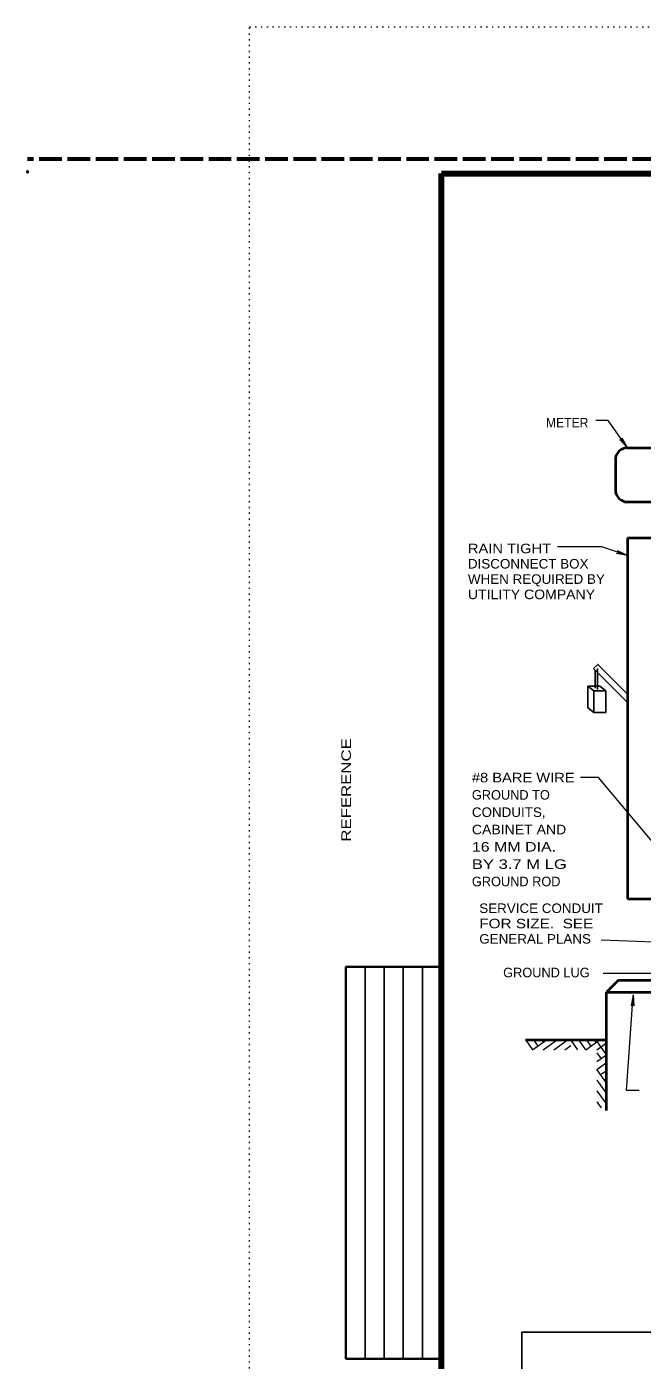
# Model space of a CAD drawing. Extents: x 312583 to 312854, y 144419 to 144597.
# Drawn here: x 312583.5 to 312632.5, y 144490.5 to 144596.8 of the extents above; entities that cross this region are included whole.
import ezdxf

# ---------------------------------------------------------------- set-up
doc = ezdxf.new("R2010")
doc.units = 0
doc.header["$LTSCALE"] = 0.3
doc.header["$PDMODE"] = 32
doc.header["$PDSIZE"] = 0.15
doc.linetypes.add('DOTTED', pattern=[1.5, 0.3, -1.2])
doc.linetypes.add('LONG_DASHED', pattern=[7.5, 6, -1.5])
doc.layers.add('1', color=7, linetype='Continuous', lineweight=25)
doc.layers.add('2', color=7, linetype='Continuous', lineweight=13)

msp = doc.modelspace()

# ---------------------------------------------------------------- linework, layer by layer
at = {"layer": '1', "linetype": 'DOTTED', "lineweight": 13}
for p, q in [((312601.2, 144596.7846), (312853.5, 144596.7846)), ((312601.2, 144418.5846), (312601.2, 144596.7846))]:
    msp.add_line(p, q, dxfattribs=at)
at = {"layer": '1', "linetype": 'LONG_DASHED', "lineweight": 60}
msp.add_line((312851.75, 144586.2246), (312583.526, 144586.2246), dxfattribs=at)
at = {"layer": '1', "lineweight": 158}
for p, q in [((312616.5, 144585.0846), (312849, 144585.0846)), ((312616.5, 144423.1446), (312616.5, 144585.0846))]:
    msp.add_line(p, q, dxfattribs=at)
at = {"layer": '1', "lineweight": 40}
for p, q in [((312631.3068, 144563.23), (312634.1818, 144563.23)), ((312630.3485, 144562.2716), (312630.3485, 144559.8796)), ((312631.3068, 144558.9213), (312634.1818, 144558.9213)), ((312631.3068, 144556.0616), (312631.3068, 144527.2963)), ((312631.3068, 144556.0616), (312636.8345, 144556.0616)), ((312631.3068, 144527.2963), (312636.8345, 144527.2963)), ((312630.5861, 144520.8256), (312629.6278, 144519.8673)), ((312629.6278, 144510.422), (312629.6278, 144519.8673)), ((312629.6278, 144519.8673), (312704.3778, 144519.8673)), ((312630.5861, 144520.8256), (312703.4195, 144520.8256)), ((312629.6278, 144516.034), (312623.1878, 144516.034))]:
    msp.add_line(p, q, dxfattribs=at)
at = {"layer": '1'}
for p, q in [((312631.3068, 144542.9363), (312628.6005, 144545.6426)), ((312628.7308, 144544.094), (312628.7308, 144545.5123)), ((312628.9301, 144545.6503), (312628.9301, 144543.9713)), ((312628.6235, 144543.864), (312628.1635, 144544.232)), ((312629.5818, 144543.864), (312629.1218, 144544.232)), ((312629.5818, 144543.864), (312628.6235, 144543.864)), ((312629.5818, 144543.864), (312629.5818, 144542.1313)), ((312628.6235, 144542.1313), (312628.1635, 144542.507)), ((312610.4087, 144490.6573), (312610.4087, 144521.8756)), ((312611.9315, 144490.6573), (312611.9315, 144521.8756)), ((312613.4543, 144490.6573), (312613.4543, 144521.8756)), ((312614.9772, 144490.6573), (312614.9772, 144521.8756)), ((312622.9059, 144492.7843), (312688.4513, 144492.7843)), ((312622.9059, 144492.7843), (312622.9059, 144445.8337))]:
    msp.add_line(p, q, dxfattribs=at)
at = {"layer": '1', "lineweight": 13}
msp.add_line((312639.8398, 144524.0303), (312628.9915, 144536.9563), dxfattribs=at)
at = {"layer": '1'}
for points in [[(312631.3068, 144543.611), (312628.9455, 144545.98), (312628.6005, 144545.6426)], [(312628.1635, 144542.507), (312628.1635, 144544.232), (312629.1218, 144544.232)], [(312628.6235, 144543.864), (312628.6235, 144542.1313), (312629.5818, 144542.1313)]]:
    msp.add_lwpolyline(points, dxfattribs=at)
at = {"layer": '1', "lineweight": 35}
msp.add_lwpolyline([(312616.5, 144490.6573), (312608.8858, 144490.6573), (312608.8858, 144521.8756), (312616.5, 144521.8756)], dxfattribs=at)
at = {"layer": '1', "lineweight": 40}
for centre, start, end in [((312631.3058, 144562.2735), 90, 180), ((312631.3058, 144559.8777), 180, 270)]:
    msp.add_arc(centre, 0.9583, start, end, dxfattribs=at)
at = {"layer": '1'}
msp.add_point((312583.526, 144585.2246), dxfattribs=at)
at = {"layer": '2'}
for p, q in [((312629.7658, 144565.4073), (312628.7998, 144565.4073)), ((312631.3068, 144563.23), (312629.7658, 144565.4073)), ((312630.7165, 144563.8816), (312630.9618, 144563.713)), ((312631.3068, 144563.23), (312630.7165, 144563.8816)), ((312630.8928, 144564.0043), (312630.9618, 144563.713)), ((312631.3068, 144563.23), (312630.8928, 144564.0043)), ((312629.2751, 144555.3333), (312625.7331, 144555.3333)), ((312631.3068, 144554.6433), (312629.2751, 144555.3333)), ((312630.5248, 144555.0266), (312630.7471, 144554.835)), ((312631.3068, 144554.6433), (312630.5248, 144555.0266)), ((312630.4481, 144554.8196), (312630.7471, 144554.835)), ((312631.3068, 144554.6433), (312630.4481, 144554.8196)), ((312628.9915, 144536.9563), (312627.5655, 144536.9563)), ((312634.9868, 144523.7773), (312629.2291, 144524.0073)), ((312631.2455, 144512.0166), (312631.7668, 144519.6066)), ((312631.7668, 144519.6373), (312631.6058, 144518.7786)), ((312631.6058, 144518.7786), (312631.7285, 144519.047)), ((312631.8205, 144518.7633), (312631.7285, 144519.047)), ((312631.7668, 144519.6373), (312631.8205, 144518.7633)), ((312623.2185, 144516.034), (312623.7551, 144515.275)), ((312623.7551, 144515.275), (312624.8438, 144516.0493)), ((312623.8395, 144516.034), (312624.1768, 144515.5663)), ((312624.4681, 144516.034), (312624.5908, 144515.8653)), ((312624.5908, 144515.275), (312625.6335, 144516.011)), ((312625.4341, 144515.275), (312626.4998, 144516.034)), ((312626.3158, 144515.275), (312626.7988, 144515.62)), ((312626.7988, 144516.0263), (312627.3431, 144515.2596)), ((312627.4275, 144516.0263), (312627.9641, 144515.2596)), ((312627.9871, 144515.275), (312629.0528, 144516.034)), ((312628.0485, 144516.0263), (312628.3858, 144515.5586)), ((312628.6771, 144516.0263), (312628.7998, 144515.8576)), ((312628.8688, 144515.919), (312629.6278, 144514.8533)), ((312628.8688, 144515.275), (312629.6278, 144515.8193)), ((312628.8688, 144515.0373), (312629.2138, 144514.5543)), ((312629.6278, 144514.8533), (312628.8688, 144514.309)), ((312629.6278, 144514.2246), (312628.8688, 144513.6803)), ((312628.8688, 144513.6803), (312629.6431, 144512.5916)), ((312629.6278, 144513.596), (312629.1601, 144513.2663)), ((312628.8688, 144512.8446), (312629.6048, 144511.8096)), ((312629.6278, 144512.9673), (312629.4591, 144512.8446)), ((312628.8688, 144512.0013), (312629.6278, 144510.9356)), ((312632.2498, 144512.0166), (312631.2455, 144512.0166)), ((312628.8688, 144511.1273), (312629.2138, 144510.6366))]:
    msp.add_line(p, q, dxfattribs=at)
for points in [[(312629.3671, 144521.3776), (312637.8925, 144521.37), (312637.3175, 144522.0983)], [(312629.2981, 144516.034), (312629.2981, 144516.0416), (312629.4131, 144516.0723), (312629.4285, 144516.034)]]:
    msp.add_lwpolyline(points, dxfattribs=at)

# ---------------------------------------------------------------- texts
at = {"layer": '1', "width": 1.3}
msp.add_text('REFERENCE                                                              ', height=0.7682, rotation=90, dxfattribs=at).set_placement((312609.2854, 144531.8549))
at = {"layer": '1'}
for s, p in [('GROUND TO', (312618.9169, 144535.1996)), ('GROUND ROD', (312618.9169, 144528.2996))]:
    msp.add_text(s, height=0.76, dxfattribs=at).set_placement(p)
for s, width, p in [('CONDUITS,', 1.05, (312618.9169, 144533.8196)), ('CABINET AND', 1.1, (312618.9169, 144532.4396)), ('16 MM DIA.', 1.25, (312618.9169, 144531.0596)), ('BY 3.7 M LG', 1.3, (312618.9169, 144529.6796))]:
    msp.add_text(s, height=0.76, dxfattribs=dict(at, width=width)).set_placement(p)
at = {"layer": '2'}
for s, width, p in [('METER', 0.95, (312624.8232, 144564.8498)), ('RAIN TIGHT', 1.15, (312618.6008, 144554.8324)), ('DISCONNECT BOX', 1.05, (312618.6008, 144553.6124)), ('WHEN REQUIRED BY', 1.05, (312618.6008, 144552.3924)), ('UTILITY COMPANY', 1.1, (312618.6008, 144551.1724)), ('#8 BARE WIRE', 1.15, (312618.9169, 144536.5796)), ('SERVICE CONDUIT', 1.05, (312619.5061, 144526.1684)), ('FOR SIZE.  SEE', 1.2, (312619.5061, 144524.9484)), ('GENERAL PLANS', 1.05, (312619.5061, 144523.7284))]:
    msp.add_text(s, height=0.76, dxfattribs=dict(at, width=width)).set_placement(p)
msp.add_text('GROUND LUG', height=0.76, dxfattribs=at).set_placement((312621.4096, 144521.047))

doc.saveas('drawing.dxf')
